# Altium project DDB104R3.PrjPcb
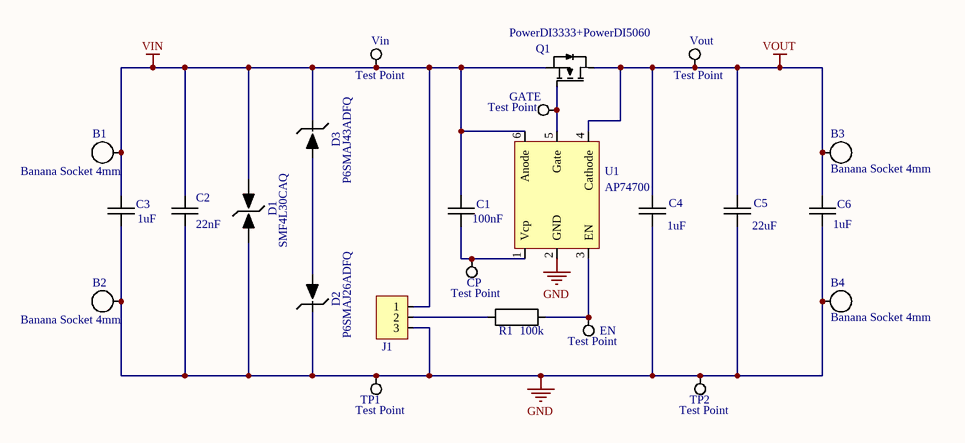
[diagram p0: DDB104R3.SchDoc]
1 sheet, 24 parts. Net scope: global (net labels, ports and power ports of the same name join across sheets).
Board file: DDB104R3.PcbDoc

## Sheet DDB104R3.SchDoc
size A4

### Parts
B1  Banana Socket 4mm  [Banana Plug]
B2  Banana Socket 4mm  [Banana Plug]
B3  Banana Socket 4mm  [Banana Plug]
B4  Banana Socket 4mm  [Banana Plug]
C1  Capacitor  [0805]  (value not drawn)
C2  Capacitor  [0805]  (value not drawn)
C3  Capacitor  [0805]  (value not drawn)
C4  Capacitor  [0805]  (value not drawn)
C5  Capacitor  [Case F Cap]  (value not drawn)
C6  Capacitor  [0805]  (value not drawn)
CP  Test Point  [TestPoint]
D1  SMF4L30CAQ  [SMF4Lxx(C)AQ]
D2  P6SMAJ26ADFQ  [P6SMAJxxADFQ]
D3  P6SMAJ43ADFQ  [P6SMAJxxADFQ]
EN  Test Point  [TestPoint]
GATE  Test Point  [TestPoint]
J1  3W header  [0.1" 3W]  (value not drawn)
Q1  PowerDI3333+PowerDI5060  [PowerDI3333+5060]
R1  Resistance  [0603]  (value not drawn)
TP1  Test Point  [TestPoint]
TP2  Test Point  [TestPoint]
U1  AP74700  [SOT26]
Vin  Test Point  [TestPoint]
Vout  Test Point  [TestPoint]

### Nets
GND: B2.1 B4.1 C2.1 C3.1 C4.1 C5.2 C6.1 D1.1 D2.0 J1.3 TP1.1 TP2.1 U1.2(GND)
VIN: B1.1 C1.2 C2.2 C3.2 D1.0 D3.0 J1.1 Q1.1 U1.6(Anode) Vin.1
VOUT: B3.1 C4.2 C5.1 C6.2 Q1.3 U1.4(Cathode) Vout.1
NetC1_1: C1.1 CP.1 U1.1(Vcp)
NetD2_1: D2.1 D3.1
NetEN_1: EN.1 R1.2 U1.3(EN)
NetGATE_1: GATE.1 Q1.2 U1.5(Gate)
NetJ1_2: J1.2 R1.1

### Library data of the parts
D1 = SMF4Lxx(C)AQ: TVS Device
D2 D3 = P6SMAJxxADFQ: TVS Device
Q1 = N-Channel MOSFET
